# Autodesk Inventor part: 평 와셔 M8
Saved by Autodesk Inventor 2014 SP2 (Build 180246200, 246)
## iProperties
Created: 2025-07
Part Number: 평 와셔 M8
Material: Generic
Document SubType Name: Modeling
Designer: Administrator
Density: 1 g/cm^3
Appearance: Default
Author: Administrator
Author: jhkim
Description: 평면 와셔
Creation Date: 2025-06-11
Sending System: Autodesk Inventor 2026
Preprocessor: ST-DEVELOPER v20.1
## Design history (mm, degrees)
node "평 와셔 M81"
body "Solid1"
node "기준1"
